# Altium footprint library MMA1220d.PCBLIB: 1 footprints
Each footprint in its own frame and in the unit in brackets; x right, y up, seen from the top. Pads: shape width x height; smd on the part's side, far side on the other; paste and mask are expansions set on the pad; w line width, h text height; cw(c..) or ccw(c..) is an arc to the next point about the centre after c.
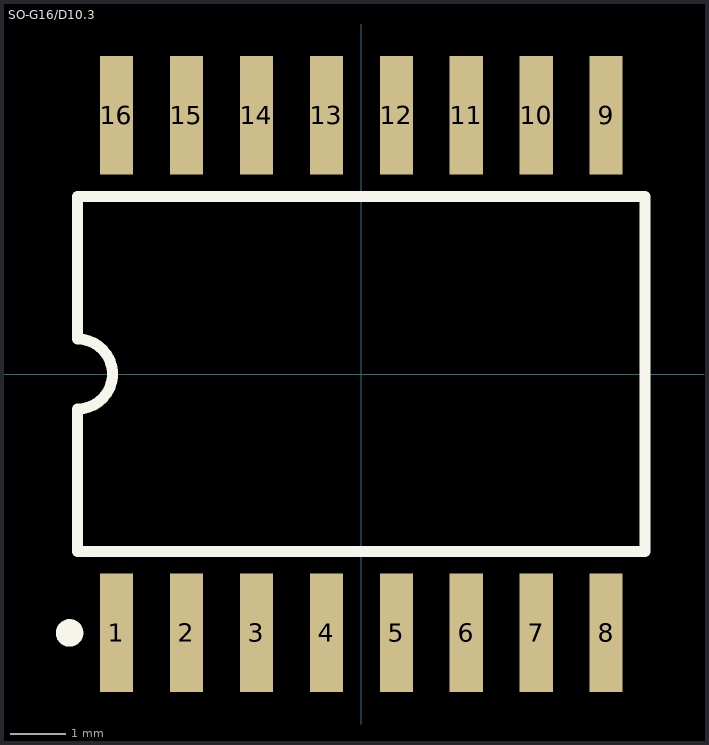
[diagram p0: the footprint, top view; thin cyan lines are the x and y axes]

## SO-G16/D10.3 [mm]
pads (16):
  rect 0.6x2.15 smd: 1(-4.445,-4.7) 2(-3.175,-4.7) 3(-1.905,-4.7) 4(-0.635,-4.7) 5(0.635,-4.7) 6(1.905,-4.7) 7(3.175,-4.7) 8(4.445,-4.7) 9(4.445,4.7) 10(3.175,4.7) 11(1.905,4.7) 12(0.635,4.7) 13(-0.635,4.7) 14(-1.905,4.7) 15(-3.175,4.7) 16(-4.445,4.7)
Top Overlay:
  circle w0.25: c-5.295,-4.7 r0.125
  lines w0.2: -5.15,-3.225 5.15,-3.225 5.15,3.225 -5.15,3.225 -5.15,0.635 cw(c-5.15,0) -5.15,-0.635 -5.15,-3.225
